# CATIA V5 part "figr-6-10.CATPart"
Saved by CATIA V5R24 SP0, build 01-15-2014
Part number: Part1
Bounding box of the stored display mesh (mm): x -25 to 25, y -75 to 75, z 0 to 20
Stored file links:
  D:\KAVITA\CATIA V5-6R2014 Project_ Kavita\CATIA V5-6R2014_partfiles\Partfiles\c06_catia_v5-6r2014_prt\figr-6-10.CATPart
  C:\Program Files\Dassault Systemes\B13\intel_a\reffiles\standard\MetricThinPitch.txt
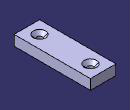
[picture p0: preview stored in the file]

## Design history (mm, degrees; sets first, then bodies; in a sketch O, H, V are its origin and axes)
Body1 (main body)
  Sketch1 on xy-plane, origin (0, 0, 0), H (1, 0, 0), V (0, 1, 0)
    line L1 (-25, 75) -> (25, 75)
    line L2 (25, 75) -> (25, -75)
    line L3 (25, -75) -> (-25, -75)
    line L4 (-25, -75) -> (-25, 75)
    axis line L5 (25, -75) -> (-25, 75)
    length L2 = 150
    length L3 = 50
    horizontal: L1 H, L3 H
    vertical: L2 V, L4 V
    midpoint: O L5
  Pad1: profile Sketch1, direction (0, 0, 1), length 20
  Sketch2 on face of Pad1, origin (-8.6664, -28.8348, 20), H (1, 0, 0), V (0, 1, 0)
    point P1 (8.6664, -21.1652)
    reference projected line E1 (-16.3336, -46.1652) -> (33.6664, -46.1652) from edge [face of Pad1 | face of Pad1]
    reference projected line E2 (-16.3336, 103.8348) -> (-16.3336, -46.1652) from edge [face of Pad1 | face of Pad1]
    distance P1 E1 = 25
    distance P1 E2 = 25
  Hole1: placed by Sketch2, at (0, -50, 20) direction (0, 0, -1), diameter 10.647, through (limit type 3), countersink depth 6, countersink angle 90
  Sketch3 on face of Pad1, origin (3.6925, 50.8892, 20), H (1, 0, 0), V (0, 1, 0)
    point P1 (-3.6925, -0.8892)
    reference projected line E1 (-28.6925, 24.1108) -> (-28.6925, -125.8892) from edge [face of Pad1 | face of Pad1]
    reference projected line E2 (21.3075, 24.1108) -> (-28.6925, 24.1108) from edge [face of Pad1 | face of Pad1]
    distance P1 E1 = 25
    distance E2 P1 = 25
  Hole2: placed by Sketch3, at (0, 50, 20) direction (0, 0, -1), diameter 10.647, through (limit type 3), countersink depth 6, countersink angle 90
